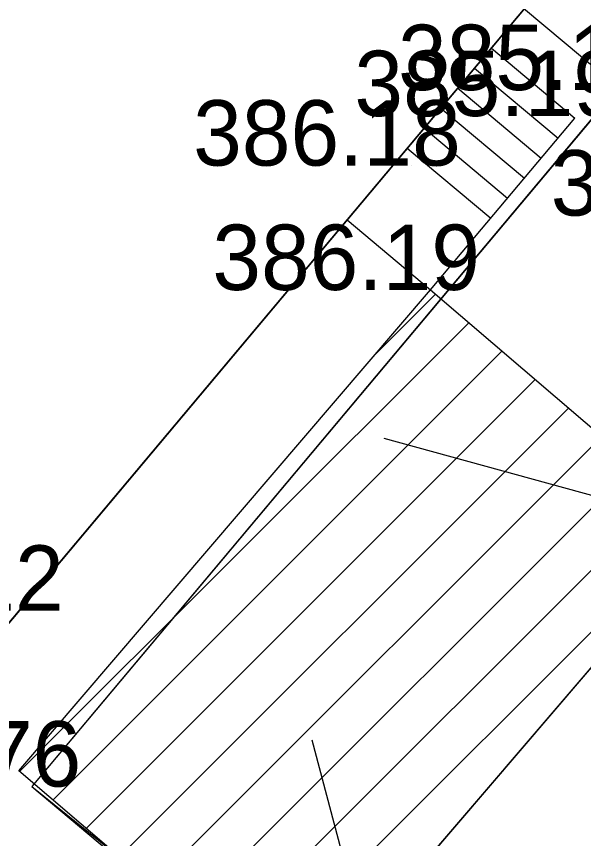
# Model space of a CAD drawing. Extents: x -438233 to -437334, y -1133133 to -1132623.
# Drawn here: x -438097.02 to -438090.52, y -1133010.11 to -1133000.68 of the extents above; entities that cross this region are included whole.
import ezdxf

# ---------------------------------------------------------------- set-up
doc = ezdxf.new("R2010")
doc.units = 0
for name, color, linetype in [('Vrstva 1', 7, 'Continuous'), ('Vrstva 10', 7, 'Continuous'), ('Vrstva 11', 7, 'Continuous'), ('Vrstva 3', 7, 'Continuous'), ('Vrstva 40', 7, 'Continuous'), ('Vrstva 5', 7, 'Continuous'), ('Vrstva 55', 7, 'Continuous')]:
    doc.layers.add(name, color=color, linetype=linetype)

msp = doc.modelspace()

# ---------------------------------------------------------------- linework, layer by layer
at = {"layer": 'Vrstva 1'}
for p, q in [((-438091.21, -1133000.582), (-438090.1267, -1133001.4895)), ((-438090.1267, -1133001.4895), (-438096.846, -1133009.51)), ((-438090.647, -1133001.819), (-438090.647, -1133001.819)), ((-438092.495, -1133002.387), (-438092.495, -1133002.387)), ((-438092.275, -1133003.814), (-438092.275, -1133003.814)), ((-438096.846, -1133009.51), (-438096.846, -1133009.51)), ((-438096.846, -1133009.51), (-438083.8202, -1133020.4226))]:
    msp.add_line(p, q, dxfattribs=at)
at = {"layer": 'Vrstva 10'}
msp.add_lwpolyline([(-438136.916, -1132976.04), (-438130.815, -1132968.777), (-438110.909, -1132985.383), (-438109.206, -1132983.342), (-438101.698, -1132989.616), (-438102.771, -1132990.9), (-438091.189, -1133000.578), (-438097.908, -1133008.583)], close=True, dxfattribs=at)
at = {"layer": 'Vrstva 11'}
for p, q in [((-438091.576, -1133001.039), (-438090.619, -1133001.842)), ((-438091.769, -1133001.269), (-438090.812, -1133002.072)), ((-438091.962, -1133001.499), (-438091.005, -1133002.302)), ((-438092.155, -1133001.728), (-438091.198, -1133002.531)), ((-438092.275, -1133003.814), (-438090.619, -1133001.842)), ((-438092.347, -1133001.958), (-438091.39, -1133002.761)), ((-438092.54, -1133002.188), (-438091.583, -1133002.991)), ((-438093.231, -1133003.011), (-438092.275, -1133003.814))]:
    msp.add_line(p, q, dxfattribs=at)
for points in [[(-438088.396, -1133002.96), (-438090.146, -1133001.521), (-438096.846, -1133009.51)], [(-438096.846, -1133009.51), (-438088.147, -1133016.523)]]:
    msp.add_lwpolyline(points, dxfattribs=at)
at = {"layer": 'Vrstva 40'}
for p, q in [((-438092.9151, -1133004.5618), (-438092.2169, -1133003.8637)), ((-438096.9845, -1133009.3384), (-438091.8359, -1133004.1898)), ((-438096.6035, -1133009.6645), (-438091.4549, -1133004.5159)), ((-438096.2225, -1133009.9906), (-438091.0739, -1133004.842)), ((-438095.8415, -1133010.3167), (-438090.6929, -1133005.1681)), ((-438095.4605, -1133010.6428), (-438090.3119, -1133005.4942)), ((-438095.0795, -1133010.9689), (-438089.9309, -1133005.8203)), ((-438094.6985, -1133011.295), (-438089.5499, -1133006.1464)), ((-438094.3175, -1133011.6211), (-438089.1689, -1133006.4725))]:
    msp.add_line(p, q, dxfattribs=at)
msp.add_lwpolyline([(-438092.275, -1133003.814), (-438089.0727, -1133006.5549), (-438093.793, -1133012.07), (-438096.9954, -1133009.3291)], close=True, dxfattribs=at)
for points in [[(-438092.275, -1133003.814), (-438089.0727, -1133006.5549), (-438093.7822, -1133012.0574)], [(-438093.636, -1133008.9754), (-438086.3458, -1133036.4844), (-438083.9887, -1133036.4844)]]:
    msp.add_lwpolyline(points, dxfattribs=at)
at = {"layer": 'Vrstva 5'}
msp.add_line((-438097.908, -1133008.583), (-438091.189, -1133000.578), dxfattribs=at)
at = {"layer": 'Vrstva 55'}
msp.add_lwpolyline([(-438092.81, -1133005.512), (-438076.859, -1133009.896)], dxfattribs=at)

# ---------------------------------------------------------------- texts
at = {"layer": 'Vrstva 3'}
for s, p in [('385.18 ', (-438092.646, -1133001.521)), ('385.19 ', (-438093.147, -1133001.819)), ('386.18 ', (-438094.995, -1133002.387)), ('385.13 ', (-438090.896, -1133002.96)), ('386.19 ', (-438094.775, -1133003.814)), ('386.12 ', (-438099.547, -1133007.494)), ('385.76 ', (-438099.346, -1133009.51))]:
    msp.add_text(s, height=0.75, dxfattribs=at).set_placement(p)

doc.saveas('drawing.dxf')
